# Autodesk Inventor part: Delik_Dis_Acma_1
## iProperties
Company: Autodesk, Inc.
Created: 2004-06
Part Number: Delik_Dis_Acma_1
Document SubType Name: Modeling
Designer: Autodesk
Manufacturer: Standard
Standards Organization: Custom
Density: 1 g/cm^3
Author: Autodesk
Subject: Autodesk Inventor
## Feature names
1. Extrusion1
2. Extrusion2
3. Extrusion3
4. Extrusion4
5. Extrusion5
6. Fillet1
7. Circular Pattern1
8. Revolution1
9. Extrusion6
10. Extrusion7
11. Fillet2
12. Mirror1
13. Extrusion8
14. Hole1
15. Hole2
